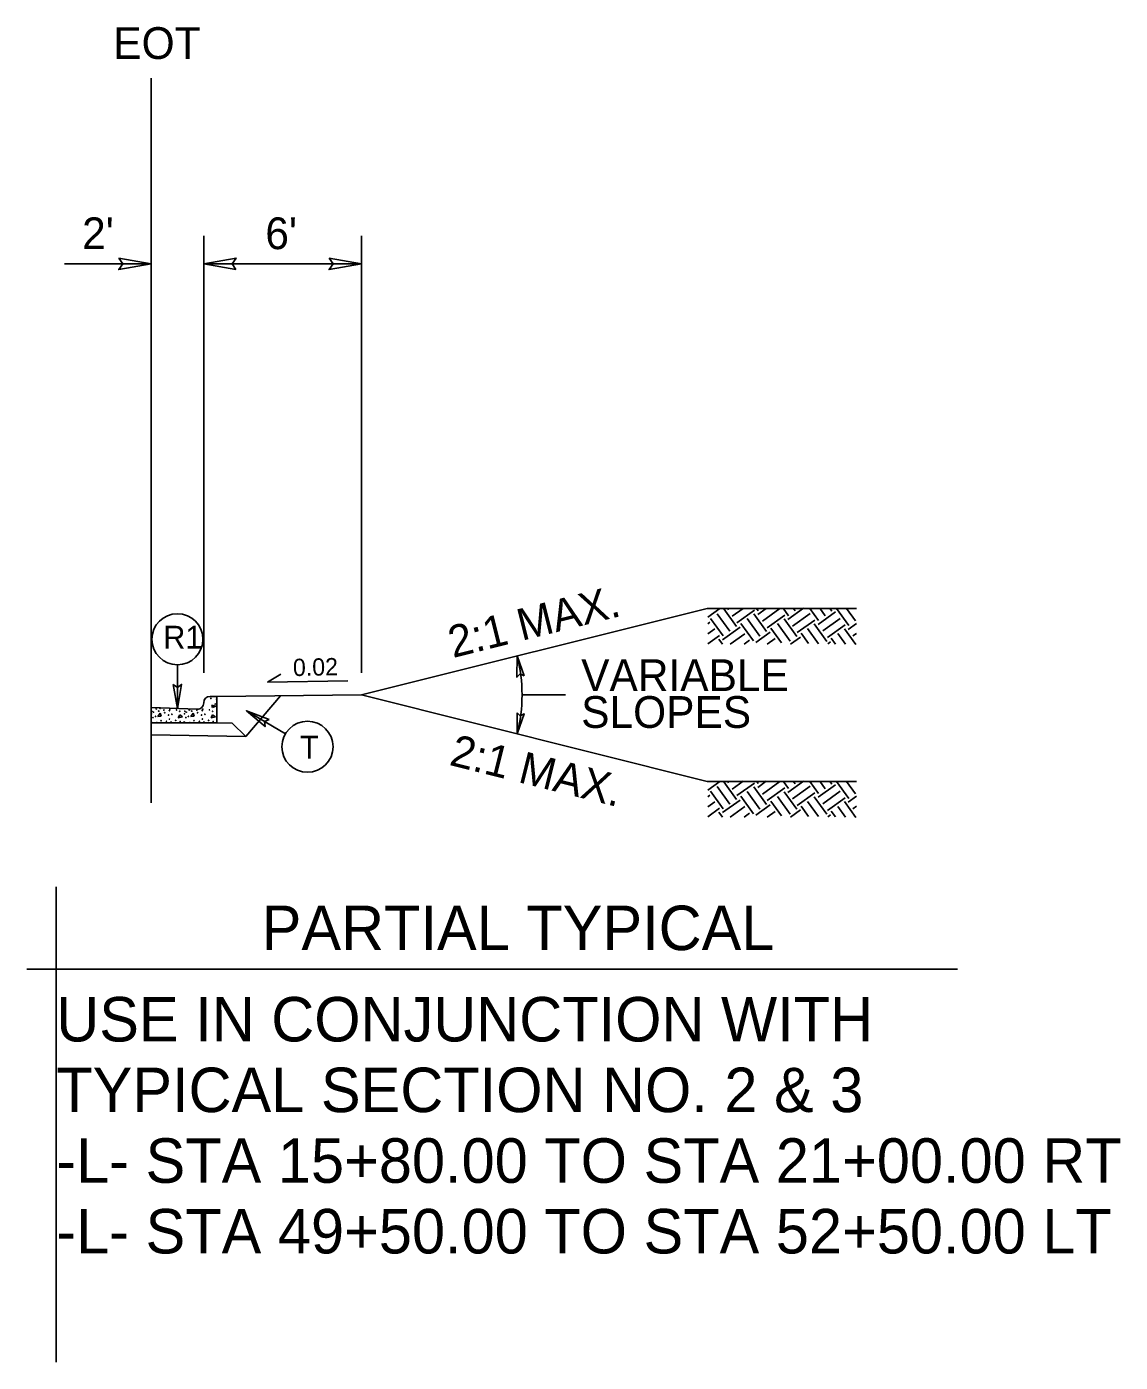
# Model space of a CAD drawing. Extents: x 3025871 to 3026431, y 707165 to 707825.
# Drawn here: x 3025960.2 to 3026001.9, y 707578.8 to 707629.7 of the extents above; entities that cross this region are included whole.
import ezdxf

# ---------------------------------------------------------------- set-up
doc = ezdxf.new("R2010")
doc.units = 0
for name, color, linetype in [('Prop Drainage Structure Junction Box with Manhole CELL', 7, 'Continuous'), ('Prop Drainage Structure Junction Box with Slab Lid TB 840 34 CELL', 7, 'Continuous'), ('Prop Drainage Structure Plot Symbol 50 Scale', 7, 'Continuous'), ('Sheet Plot Border Inside CELL', 7, 'Continuous'), ('Sheet Sticker Incomplete CELL', 7, 'Continuous'), ('Sheet Typical CELL', 7, 'Continuous'), ('Typical Arrow Superelevation CELL', 7, 'Continuous'), ('Typical Grade Point Symbol CELL', 7, 'Continuous'), ('Typical Pavement Slope Information CELL', 7, 'Continuous'), ('Typical Shoulder Slope CELL', 7, 'Continuous'), ('Typical Text Centerline CELL', 7, 'Continuous'), ('Typical Text Grade Point CELL', 7, 'Continuous')]:
    doc.layers.add(name, color=color, linetype=linetype)

msp = doc.modelspace()

# ---------------------------------------------------------------- linework, layer by layer
at = {"layer": 'Prop Drainage Structure Junction Box with Manhole CELL'}
msp.add_line((3025964.948, 707602.705), (3025968.559, 707602.633), dxfattribs=at)
at = {"layer": 'Prop Drainage Structure Junction Box with Slab Lid TB 840 34 CELL'}
for p, q in [((3025966.957, 707605.059), (3025966.957, 707621.699)), ((3025972.957, 707605.059), (3025972.957, 707621.699)), ((3025961.654, 707620.632), (3025964.948, 707620.632)), ((3025966.957, 707620.632), (3025972.957, 707620.632)), ((3025979.072, 707604.219), (3025980.728, 707604.219)), ((3025960.214, 707593.776), (3025995.654, 707593.776))]:
    msp.add_line(p, q, dxfattribs=at)
msp.add_arc((3025972.957, 707604.219), 6.116, 345.9638, 14.0362, dxfattribs=at)
at = {"layer": 'Prop Drainage Structure Plot Symbol 50 Scale'}
for p, q in [((3025964.948, 707603.162), (3025964.948, 707603.747)), ((3025964.948, 707603.747), (3025966.705, 707603.674)), ((3025966.955, 707603.914), (3025966.955, 707603.925)), ((3025967.457, 707604.165), (3025967.196, 707604.165)), ((3025967.266, 707603.831), (3025967.282, 707603.74)), ((3025967.42, 707603.786), (3025967.266, 707603.831)), ((3025967.282, 707603.74), (3025967.42, 707603.786)), ((3025967.457, 707603.162), (3025967.457, 707604.165)), ((3025967.457, 707603.162), (3025964.948, 707603.162)), ((3025965.21, 707603.402), (3025965.296, 707603.522)), ((3025965.331, 707603.408), (3025965.21, 707603.402)), ((3025965.296, 707603.522), (3025965.331, 707603.408)), ((3025965.978, 707603.351), (3025966.041, 707603.466)), ((3025966.144, 707603.391), (3025965.978, 707603.351)), ((3025966.041, 707603.466), (3025966.144, 707603.391)), ((3025966.464, 707603.402), (3025966.55, 707603.522)), ((3025966.584, 707603.408), (3025966.464, 707603.402)), ((3025966.55, 707603.522), (3025966.584, 707603.408)), ((3025967.231, 707603.351), (3025967.294, 707603.466)), ((3025967.397, 707603.391), (3025967.231, 707603.351)), ((3025967.294, 707603.466), (3025967.397, 707603.391))]:
    msp.add_line(p, q, dxfattribs=at)
for centre in [(3025965.147, 707603.688), (3025965.29, 707603.705), (3025965.663, 707603.677), (3025966.916, 707603.677), (3025967.226, 707604.089), (3025967.392, 707603.871), (3025967.444, 707604.055), (3025964.959, 707603.19), (3025964.965, 707603.5), (3025964.982, 707603.597), (3025965.022, 707603.357), (3025965.038, 707603.563), (3025965.119, 707603.402), (3025965.17, 707603.168), (3025965.244, 707603.603), (3025965.33, 707603.236), (3025965.439, 707603.642), (3025965.468, 707603.54), (3025965.537, 707603.213), (3025965.617, 707603.454), (3025965.646, 707603.626), (3025965.651, 707603.299), (3025965.709, 707603.185), (3025965.743, 707603.483), (3025965.886, 707603.248), (3025965.92, 707603.648), (3025966.041, 707603.597), (3025966.058, 707603.208), (3025966.213, 707603.19), (3025966.218, 707603.5), (3025966.236, 707603.597), (3025966.276, 707603.357), (3025966.292, 707603.563), (3025966.372, 707603.402), (3025966.401, 707603.646), (3025966.424, 707603.168), (3025966.498, 707603.603), (3025966.584, 707603.236), (3025966.693, 707603.642), (3025966.722, 707603.54), (3025966.79, 707603.213), (3025966.871, 707603.454), (3025966.899, 707603.626), (3025966.905, 707603.299), (3025966.962, 707603.185), (3025966.997, 707603.483), (3025967.14, 707603.248), (3025967.174, 707603.648), (3025967.294, 707603.597), (3025967.312, 707603.208)]:
    msp.add_circle(centre, 0.00805, dxfattribs=at)
for centre, start, end in [((3025966.715, 707603.914), 267.6155, 0), ((3025967.196, 707603.925), 90, 180)]:
    msp.add_arc(centre, 0.24, start, end, dxfattribs=at)
at = {"layer": 'Sheet Plot Border Inside CELL'}
msp.add_line((3025968.042, 707603.15), (3025967.457, 707603.162), dxfattribs=at)
at = {"layer": 'Sheet Sticker Incomplete CELL'}
for q in [(3025969.893, 707605.011), (3025972.445, 707604.761)]:
    msp.add_line((3025969.378, 707604.7), q, dxfattribs=at)
at = {"layer": 'Sheet Typical CELL'}
for p, q in [((3025967.457, 707604.165), (3025972.957, 707604.219)), ((3025968.559, 707602.633), (3025969.882, 707604.189)), ((3025968.042, 707603.15), (3025968.559, 707602.633))]:
    msp.add_line(p, q, dxfattribs=at)
at = {"layer": 'Typical Grade Point Symbol CELL'}
for p, q in [((3025965.953, 707603.705), (3025965.953, 707605.367)), ((3025970.068, 707602.741), (3025968.582, 707603.617))]:
    msp.add_line(p, q, dxfattribs=at)
for centre in [(3025965.953, 707606.339), (3025970.905, 707602.247)]:
    msp.add_circle(centre, 0.972, dxfattribs=at)
at = {"layer": 'Typical Pavement Slope Information CELL'}
msp.add_line((3025961.339, 707596.919), (3025961.339, 707578.813), dxfattribs=at)
at = {"layer": 'Typical Shoulder Slope CELL'}
msp.add_line((3025964.948, 707600.106), (3025964.948, 707627.699), dxfattribs=at)
at = {"layer": 'Typical Text Centerline CELL'}
for points in [[(3025963.723, 707620.843), (3025964.948, 707620.632), (3025963.716, 707620.415), (3025963.873, 707620.632)], [(3025968.182, 707620.421), (3025966.957, 707620.632), (3025968.189, 707620.85), (3025968.032, 707620.632)], [(3025971.732, 707620.843), (3025972.957, 707620.632), (3025971.725, 707620.415), (3025971.882, 707620.632)], [(3025979.153, 707604.945), (3025978.89, 707605.702), (3025978.881, 707604.896), (3025979.003, 707605.018)], [(3025965.796, 707604.615), (3025965.953, 707603.705), (3025966.114, 707604.62), (3025965.953, 707604.504)], [(3025969.446, 707603.29), (3025968.582, 707603.617), (3025969.288, 707603.013), (3025969.27, 707603.212)], [(3025978.886, 707603.537), (3025978.89, 707602.736), (3025979.16, 707603.496), (3025979.005, 707603.42)]]:
    msp.add_lwpolyline(points, close=True, dxfattribs=at)
at = {"layer": 'Typical Text Grade Point CELL'}
for p, q in [((3025986.122, 707607.51), (3025972.957, 707604.219)), ((3025986.122, 707607.51), (3025991.807, 707607.51)), ((3025986.122, 707607.51), (3025991.807, 707607.51)), ((3025986.144, 707607.181), (3025986.604, 707607.511)), ((3025986.144, 707607.181), (3025986.604, 707607.511)), ((3025986.983, 707606.644), (3025986.503, 707607.312)), ((3025986.983, 707606.644), (3025986.503, 707607.312)), ((3025987.234, 707606.824), (3025986.754, 707607.493)), ((3025987.234, 707606.824), (3025986.754, 707607.493)), ((3025986.897, 707607.469), (3025986.958, 707607.512)), ((3025986.897, 707607.469), (3025986.958, 707607.512)), ((3025987.077, 707607.218), (3025987.489, 707607.514)), ((3025987.077, 707607.218), (3025987.489, 707607.514)), ((3025987.258, 707606.968), (3025987.926, 707607.448)), ((3025987.258, 707606.968), (3025987.926, 707607.448)), ((3025988.383, 707606.636), (3025987.902, 707607.305)), ((3025988.383, 707606.636), (3025987.902, 707607.305)), ((3025988.07, 707607.425), (3025988.004, 707607.515)), ((3025988.07, 707607.425), (3025988.004, 707607.515)), ((3025988.046, 707607.281), (3025988.374, 707607.516)), ((3025988.046, 707607.281), (3025988.374, 707607.516)), ((3025988.226, 707607.03), (3025988.895, 707607.511)), ((3025988.226, 707607.03), (3025988.895, 707607.511)), ((3025988.406, 707606.78), (3025989.075, 707607.26)), ((3025988.406, 707606.78), (3025989.075, 707607.26)), ((3025989.218, 707607.237), (3025989.016, 707607.518)), ((3025989.218, 707607.237), (3025989.016, 707607.518)), ((3025989.195, 707607.093), (3025989.79, 707607.521)), ((3025989.195, 707607.093), (3025989.79, 707607.521)), ((3025989.375, 707606.842), (3025990.043, 707607.323)), ((3025989.375, 707606.842), (3025990.043, 707607.323)), ((3025989.469, 707607.417), (3025989.395, 707607.519)), ((3025989.469, 707607.417), (3025989.395, 707607.519)), ((3025990.367, 707607.048), (3025990.035, 707607.51)), ((3025990.367, 707607.048), (3025990.035, 707607.51)), ((3025990.343, 707606.905), (3025991.012, 707607.385)), ((3025990.343, 707606.905), (3025991.012, 707607.385)), ((3025990.618, 707607.229), (3025990.407, 707607.522)), ((3025990.618, 707607.229), (3025990.407, 707607.522)), ((3025990.868, 707607.409), (3025990.795, 707607.51)), ((3025990.868, 707607.409), (3025990.795, 707607.51)), ((3025991.516, 707606.86), (3025991.049, 707607.51)), ((3025991.516, 707606.86), (3025991.049, 707607.51)), ((3025991.766, 707607.041), (3025991.429, 707607.51)), ((3025991.766, 707607.041), (3025991.429, 707607.51)), ((3025986.144, 707606.928), (3025986.229, 707606.989)), ((3025986.144, 707606.928), (3025986.229, 707606.989)), ((3025986.144, 707606.548), (3025986.409, 707606.738)), ((3025986.144, 707606.548), (3025986.409, 707606.738)), ((3025986.733, 707606.464), (3025986.252, 707607.132)), ((3025986.733, 707606.464), (3025986.252, 707607.132)), ((3025986.709, 707606.32), (3025987.378, 707606.801)), ((3025986.709, 707606.32), (3025987.378, 707606.801)), ((3025987.881, 707606.276), (3025987.401, 707606.944)), ((3025987.881, 707606.276), (3025987.401, 707606.944)), ((3025988.132, 707606.456), (3025987.652, 707607.124)), ((3025988.132, 707606.456), (3025987.652, 707607.124)), ((3025988.951, 707606.199), (3025988.55, 707606.756)), ((3025988.951, 707606.199), (3025988.55, 707606.756)), ((3025989.281, 707606.268), (3025988.801, 707606.936)), ((3025989.281, 707606.268), (3025988.801, 707606.936)), ((3025989.531, 707606.448), (3025989.051, 707607.116)), ((3025989.531, 707606.448), (3025989.051, 707607.116)), ((3025989.555, 707606.592), (3025990.223, 707607.072)), ((3025989.555, 707606.592), (3025990.223, 707607.072)), ((3025990.365, 707606.17), (3025989.949, 707606.748)), ((3025990.365, 707606.17), (3025989.949, 707606.748)), ((3025990.68, 707606.26), (3025990.2, 707606.928)), ((3025990.68, 707606.26), (3025990.2, 707606.928)), ((3025990.524, 707606.654), (3025991.192, 707607.135)), ((3025990.524, 707606.654), (3025991.192, 707607.135)), ((3025990.704, 707606.404), (3025991.372, 707606.884)), ((3025990.704, 707606.404), (3025991.372, 707606.884)), ((3025991.779, 707606.142), (3025991.349, 707606.74)), ((3025991.779, 707606.142), (3025991.349, 707606.74)), ((3025991.492, 707606.717), (3025991.807, 707606.943)), ((3025991.492, 707606.717), (3025991.807, 707606.943)), ((3025986.144, 707606.167), (3025986.589, 707606.487)), ((3025986.144, 707606.167), (3025986.589, 707606.487)), ((3025986.705, 707606.15), (3025986.566, 707606.344)), ((3025986.705, 707606.15), (3025986.566, 707606.344)), ((3025987.001, 707606.15), (3025987.558, 707606.55)), ((3025987.001, 707606.15), (3025987.558, 707606.55)), ((3025987.53, 707606.15), (3025987.738, 707606.299)), ((3025987.53, 707606.15), (3025987.738, 707606.299)), ((3025987.977, 707606.218), (3025988.526, 707606.613)), ((3025987.977, 707606.218), (3025988.526, 707606.613)), ((3025988.412, 707606.15), (3025988.706, 707606.362)), ((3025988.412, 707606.15), (3025988.706, 707606.362)), ((3025989.293, 707606.15), (3025989.675, 707606.425)), ((3025989.293, 707606.15), (3025989.675, 707606.425)), ((3025989.979, 707606.178), (3025989.699, 707606.568)), ((3025989.979, 707606.178), (3025989.699, 707606.568)), ((3025990.722, 707606.163), (3025990.824, 707606.236)), ((3025990.722, 707606.163), (3025990.824, 707606.236)), ((3025991.007, 707606.157), (3025990.847, 707606.38)), ((3025991.007, 707606.157), (3025990.847, 707606.38)), ((3025991.393, 707606.15), (3025991.098, 707606.56)), ((3025991.393, 707606.15), (3025991.098, 707606.56)), ((3025991.672, 707606.466), (3025991.807, 707606.563)), ((3025991.672, 707606.466), (3025991.807, 707606.563)), ((3025972.957, 707604.219), (3025986.122, 707600.928)), ((3025986.122, 707600.928), (3025991.807, 707600.928)), ((3025986.122, 707600.928), (3025991.807, 707600.928)), ((3025986.144, 707600.598), (3025986.604, 707600.929)), ((3025986.144, 707600.598), (3025986.604, 707600.929)), ((3025986.983, 707600.061), (3025986.503, 707600.73)), ((3025986.983, 707600.061), (3025986.503, 707600.73)), ((3025987.234, 707600.242), (3025986.754, 707600.91)), ((3025987.234, 707600.242), (3025986.754, 707600.91)), ((3025986.897, 707600.886), (3025986.958, 707600.93)), ((3025986.897, 707600.886), (3025986.958, 707600.93)), ((3025987.077, 707600.636), (3025987.489, 707600.931)), ((3025987.077, 707600.636), (3025987.489, 707600.931)), ((3025987.258, 707600.385), (3025987.926, 707600.866)), ((3025987.258, 707600.385), (3025987.926, 707600.866)), ((3025988.383, 707600.054), (3025987.902, 707600.722)), ((3025988.383, 707600.054), (3025987.902, 707600.722)), ((3025988.07, 707600.842), (3025988.004, 707600.933)), ((3025988.07, 707600.842), (3025988.004, 707600.933)), ((3025988.046, 707600.698), (3025988.374, 707600.934)), ((3025988.046, 707600.698), (3025988.374, 707600.934)), ((3025988.226, 707600.448), (3025988.895, 707600.928)), ((3025988.226, 707600.448), (3025988.895, 707600.928)), ((3025988.406, 707600.197), (3025989.075, 707600.677)), ((3025988.406, 707600.197), (3025989.075, 707600.677)), ((3025989.218, 707600.654), (3025989.016, 707600.936)), ((3025989.218, 707600.654), (3025989.016, 707600.936)), ((3025989.195, 707600.51), (3025989.79, 707600.938)), ((3025989.195, 707600.51), (3025989.79, 707600.938)), ((3025989.375, 707600.26), (3025990.043, 707600.74)), ((3025989.375, 707600.26), (3025990.043, 707600.74)), ((3025989.469, 707600.834), (3025989.395, 707600.937)), ((3025989.469, 707600.834), (3025989.395, 707600.937)), ((3025990.367, 707600.466), (3025990.035, 707600.928)), ((3025990.367, 707600.466), (3025990.035, 707600.928)), ((3025990.343, 707600.322), (3025991.012, 707600.803)), ((3025990.343, 707600.322), (3025991.012, 707600.803)), ((3025990.618, 707600.646), (3025990.407, 707600.94)), ((3025990.618, 707600.646), (3025990.407, 707600.94)), ((3025990.868, 707600.826), (3025990.795, 707600.928)), ((3025990.868, 707600.826), (3025990.795, 707600.928)), ((3025991.516, 707600.278), (3025991.049, 707600.928)), ((3025991.516, 707600.278), (3025991.049, 707600.928)), ((3025991.766, 707600.458), (3025991.429, 707600.928)), ((3025991.766, 707600.458), (3025991.429, 707600.928)), ((3025986.144, 707600.345), (3025986.229, 707600.406)), ((3025986.144, 707600.345), (3025986.229, 707600.406)), ((3025986.144, 707599.965), (3025986.409, 707600.156)), ((3025986.144, 707599.965), (3025986.409, 707600.156)), ((3025986.733, 707599.881), (3025986.252, 707600.55)), ((3025986.733, 707599.881), (3025986.252, 707600.55)), ((3025986.709, 707599.738), (3025987.378, 707600.218)), ((3025986.709, 707599.738), (3025987.378, 707600.218)), ((3025987.881, 707599.693), (3025987.401, 707600.362)), ((3025987.881, 707599.693), (3025987.401, 707600.362)), ((3025988.132, 707599.873), (3025987.652, 707600.542)), ((3025988.132, 707599.873), (3025987.652, 707600.542)), ((3025988.951, 707599.616), (3025988.55, 707600.174)), ((3025988.951, 707599.616), (3025988.55, 707600.174)), ((3025989.281, 707599.685), (3025988.801, 707600.354)), ((3025989.281, 707599.685), (3025988.801, 707600.354)), ((3025989.531, 707599.865), (3025989.051, 707600.534)), ((3025989.531, 707599.865), (3025989.051, 707600.534)), ((3025989.555, 707600.009), (3025990.223, 707600.489)), ((3025989.555, 707600.009), (3025990.223, 707600.489)), ((3025990.365, 707599.588), (3025989.949, 707600.166)), ((3025990.365, 707599.588), (3025989.949, 707600.166)), ((3025990.68, 707599.677), (3025990.2, 707600.346)), ((3025990.68, 707599.677), (3025990.2, 707600.346)), ((3025990.524, 707600.072), (3025991.192, 707600.552)), ((3025990.524, 707600.072), (3025991.192, 707600.552)), ((3025990.704, 707599.821), (3025991.372, 707600.301)), ((3025990.704, 707599.821), (3025991.372, 707600.301)), ((3025991.779, 707599.559), (3025991.349, 707600.158)), ((3025991.779, 707599.559), (3025991.349, 707600.158)), ((3025991.492, 707600.134), (3025991.807, 707600.36)), ((3025991.492, 707600.134), (3025991.807, 707600.36)), ((3025986.144, 707599.585), (3025986.589, 707599.905)), ((3025986.144, 707599.585), (3025986.589, 707599.905)), ((3025986.705, 707599.568), (3025986.566, 707599.761)), ((3025986.705, 707599.568), (3025986.566, 707599.761)), ((3025987.001, 707599.568), (3025987.558, 707599.967)), ((3025987.001, 707599.568), (3025987.558, 707599.967)), ((3025987.53, 707599.568), (3025987.738, 707599.717)), ((3025987.53, 707599.568), (3025987.738, 707599.717)), ((3025987.977, 707599.636), (3025988.526, 707600.03)), ((3025987.977, 707599.636), (3025988.526, 707600.03)), ((3025988.412, 707599.568), (3025988.706, 707599.779)), ((3025988.412, 707599.568), (3025988.706, 707599.779)), ((3025989.293, 707599.568), (3025989.675, 707599.842)), ((3025989.293, 707599.568), (3025989.675, 707599.842)), ((3025989.979, 707599.595), (3025989.699, 707599.986)), ((3025989.979, 707599.595), (3025989.699, 707599.986)), ((3025990.722, 707599.58), (3025990.824, 707599.654)), ((3025990.722, 707599.58), (3025990.824, 707599.654)), ((3025991.007, 707599.575), (3025990.847, 707599.797)), ((3025991.007, 707599.575), (3025990.847, 707599.797)), ((3025991.393, 707599.567), (3025991.098, 707599.978)), ((3025991.393, 707599.567), (3025991.098, 707599.978)), ((3025991.672, 707599.884), (3025991.807, 707599.98)), ((3025991.672, 707599.884), (3025991.807, 707599.98))]:
    msp.add_line(p, q, dxfattribs=at)

# ---------------------------------------------------------------- texts
at = {"layer": 'Prop Drainage Structure Junction Box with Slab Lid TB 840 34 CELL'}
for s, height, p in [('EOT', 1.2089, (3025963.511, 707628.432)), ("2'", 1.2089, (3025962.323, 707621.191)), ("6'", 1.2089, (3025969.299, 707621.191)), ('-L- STA 15+80.00 TO STA 21+00.00 RT', 1.6949, (3025961.339, 707585.646)), ('-L- STA 49+50.00 TO STA 52+50.00 LT', 1.6949, (3025961.339, 707582.956))]:
    msp.add_text(s, height=height, dxfattribs=at).set_placement(p)
for s, p in [('PARTIAL TYPICAL', (3025969.162, 707594.503)), ('USE IN CONJUNCTION WITH', (3025961.339, 707591.026)), ('TYPICAL SECTION NO. 2 & 3', (3025961.339, 707588.336))]:
    msp.add_text(s, height=1.69489, rotation=360, dxfattribs=at).set_placement(p)
at = {"layer": 'Sheet Sticker Incomplete CELL'}
msp.add_text('0.02 ', height=0.6583, rotation=1.2029, dxfattribs=at).set_placement((3025970.358, 707604.935))
at = {"layer": 'Typical Arrow Superelevation CELL'}
for s, p in [('R1', (3025965.415, 707605.982)), ('T', (3025970.621, 707601.796))]:
    msp.add_text(s, height=0.87, rotation=360, dxfattribs=at).set_placement(p)
at = {"layer": 'Typical Text Grade Point CELL'}
for rotation, p in [(14.0362, (3025976.443, 707605.621)), (345.9638, (3025976.265, 707601.561))]:
    msp.add_text('2:1 MAX.', height=1.2089, rotation=rotation, dxfattribs=at).set_placement(p)
for s, p in [('VARIABLE', (3025981.326, 707604.367)), ('SLOPES', (3025981.326, 707602.965))]:
    msp.add_text(s, height=1.2089, dxfattribs=at).set_placement(p)

doc.saveas('drawing.dxf')
